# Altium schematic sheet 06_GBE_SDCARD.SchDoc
size A2; ApprovedBy: DNP; CheckedBy: DNP; Author: DNP; CompanyName: Google LLC; DrawnBy: DNP; Engineer: Bangfei/Michael/Leo; Organization: Google LLC; Address1: 1600 Amphitheatre Parkway; Address2: Mountain View, CA 94043; Address3: DNP; Address4: DNP; DocumentNumber: DNP; Revision: PVT; SheetNumber: 6; SheetTotal: 11; VersionControl_RevNumber: DNP; IsUserConfigurable: DNP
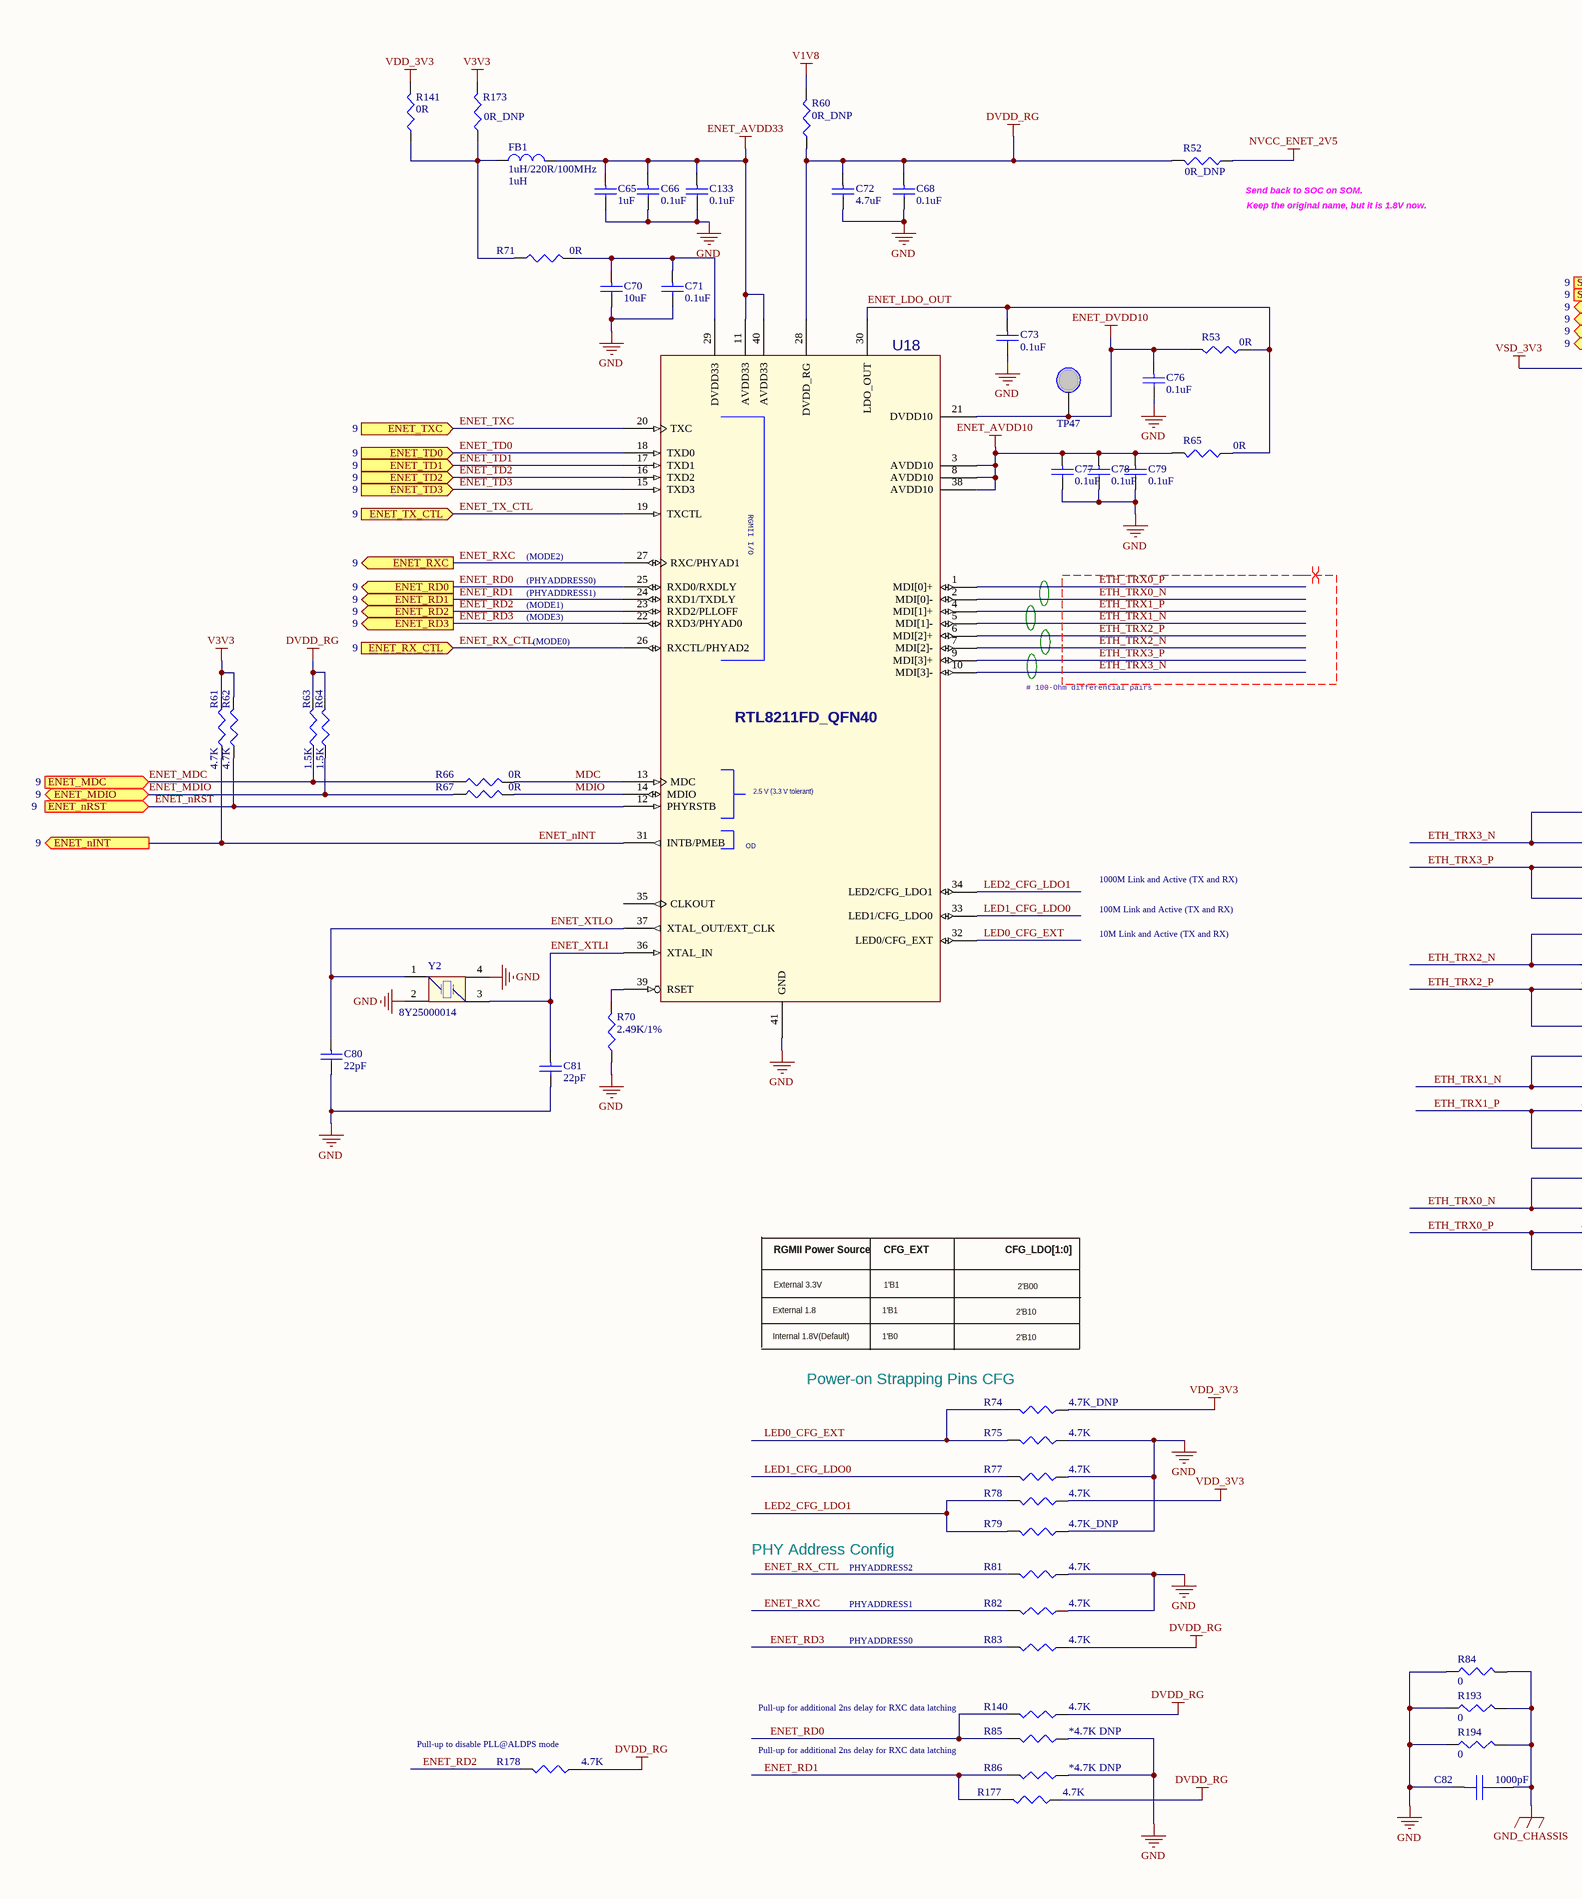
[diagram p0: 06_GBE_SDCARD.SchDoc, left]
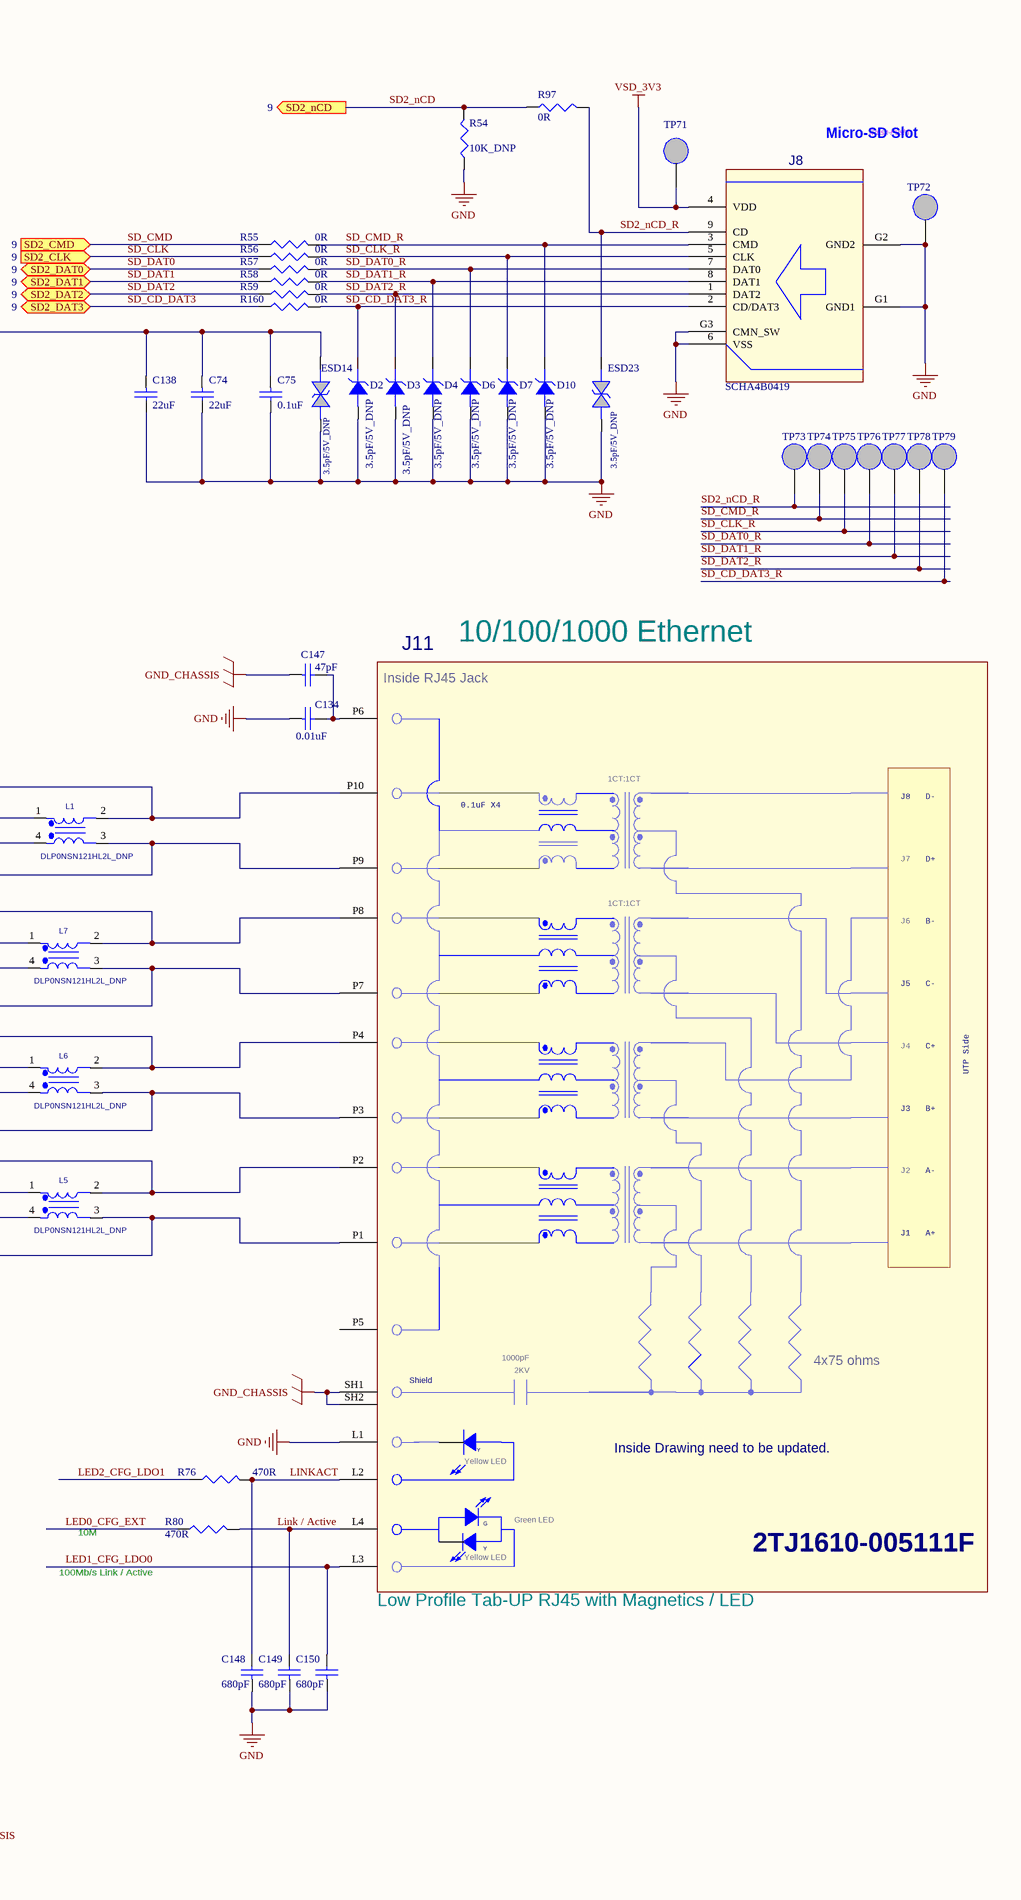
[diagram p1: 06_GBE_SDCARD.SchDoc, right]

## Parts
C65  value 1uF  [0201]  (hidden comment: 1uF/6.3V)
C66  value 0.1uF  [0201]  (hidden comment: 0.1uF/10V)
C68  value 0.1uF  [0201]  (hidden comment: 0.1uF/10V)
C70  value 10uF  [0402]  (hidden comment: 10uF/10V)
C71  value 0.1uF  [0201]  (hidden comment: 0.1uF/10V)
C72  value 4.7uF  [0402]  (hidden comment: 4.7uF/10V)
C73  value 0.1uF  [0201]  (hidden comment: 0.1uF/10V)
C74  value 22uF  [0603]  (hidden comment: 22uF/10V)
C75  value 0.1uF  [0201]  (hidden comment: 0.1uF/10V)
C76  value 0.1uF  [0201]  (hidden comment: 0.1uF/10V)
C77  value 0.1uF  [0201]  (hidden comment: 0.1uF/10V)
C78  value 0.1uF  [0201]  (hidden comment: 0.1uF/10V)
C79  value 0.1uF  [0201]  (hidden comment: 0.1uF/10V)
C80  value 22pF  [0201]  (hidden comment: 22pF/6.3V)
C81  value 22pF  [0201]  (hidden comment: 22pF/6.3V)
C82  value 1000pF  [1206]  (hidden comment: 1000pF/2KV)
C133  value 0.1uF  [0201]  (hidden comment: 0.1uF/10V)
C134  value 0.01uF  [0201]  (hidden comment: 0.01uF/25V)
C138  value 22uF  [0603]  (hidden comment: 22uF/10V)
C147  value 47pF  [0201]  (hidden comment: 47pF/25V)
C148  value 680pF  [0201]  (hidden comment: 680PF 25V)
C149  value 680pF  [0201]  (hidden comment: 680PF 25V)
C150  value 680pF  [0201]  (hidden comment: 680PF 25V)
D2  3.5pF/5V_DNP  [0201-Diode]
D3  3.5pF/5V_DNP  [0201-Diode]
D4  3.5pF/5V_DNP  [0201-Diode]
D6  3.5pF/5V_DNP  [0201-Diode]
D7  3.5pF/5V_DNP  [0201-Diode]
D10  3.5pF/5V_DNP  [0201-Diode]
ESD14  3.5pF/5V_DNP  [0201]
ESD23  3.5pF/5V_DNP  [0201]
FB1  1uH/220R/100MHz  value 1uH  [0603]
J8  SCHA4B0419  [CON9_SDCARD_8PIN_SCHA4B0419]
J11  2TJ1610-005111F  [RJ45-LED-2TJ1610-005111F]
L1  DLP0NSN121HL2L_DNP  [PL4-DLP0NSN121HL2L]
L5  DLP0NSN121HL2L_DNP  [PL4-DLP0NSN121HL2L]
L6  DLP0NSN121HL2L_DNP  [PL4-DLP0NSN121HL2L]
L7  DLP0NSN121HL2L_DNP  [PL4-DLP0NSN121HL2L]
R52  0R_DNP  [0201]
R53  0R  [0201]
R54  value 10K_DNP  [0201]  (hidden comment: 10K)
R55  0R  [0201]
R56  0R  [0201]
R57  0R  [0201]
R58  0R  [0201]
R59  0R  [0201]
R60  0R_DNP  [0201]
R61  4.7K  [0201]
R62  4.7K  [0201]
R63  1.5K  [0201]
R64  1.5K  [0201]
R65  0R  [0201]
R66  0R  [0201]
R67  0R  [0201]
R70  2.49K/1%  [0201]
R71  0R  [0201]
R74  4.7K_DNP  [0201]
R75  4.7K  [0201]
R76  470R  [0201]
R77  4.7K  [0201]
R78  4.7K  [0201]
R79  4.7K_DNP  [0201]
R80  470R  [0201]
R81  4.7K  [0201]
R82  4.7K  [0201]
R83  4.7K  [0201]
R84  value 0  [0805]  (hidden comment: R_0805_0)
R85  value *4.7K DNP  [0201]  (hidden comment: 4.7K)
R86  value *4.7K DNP  [0201]  (hidden comment: 4.7K)
R97  value 0R  [0201]  (hidden comment: 0R_DNP)
R140  value 4.7K  [0201]  (hidden comment: 4.7K_DNP)
R141  0R  [0201]
R160  0R  [0201]
R173  0R_DNP  [0201]
R177  value 4.7K  [0201]  (hidden comment: 4.7K_DNP)
R178  4.7K  [0201]
R193  value 0  [0805]  (hidden comment: R_0805_0)
R194  value 0  [0805]  (hidden comment: R_0805_0)
TP47  TP NM  [TP_SMD]  (value not drawn)  (no BOM)
TP71  TP NM  [TP_SMD]  (value not drawn)  (no BOM)
TP72  TP NM  [TP_SMD]  (value not drawn)  (no BOM)
TP73  TP NM  [TP3050]  (value not drawn)  (no BOM)
TP74  TP NM  [TP3050]  (value not drawn)  (no BOM)
TP75  TP NM  [TP3050]  (value not drawn)  (no BOM)
TP76  TP NM  [TP3050]  (value not drawn)  (no BOM)
TP77  TP NM  [TP3050]  (value not drawn)  (no BOM)
TP78  TP NM  [TP3050]  (value not drawn)  (no BOM)
TP79  TP NM  [TP3050]  (value not drawn)  (no BOM)
U18  RTL8211FD_QFN40  [QFN40-0_4-5X5-H0_9MM]
Y2  8Y25000014  [DFN130P250X50-4N]

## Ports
ENET_MDC (in, see 9), ENET_MDIO (bidir, see 9), ENET_nINT (out, see 9), ENET_nRST (in, see 9), ENET_RD0 (out, see 9), ENET_RD1 (out, see 9), ENET_RD2 (out, see 9), ENET_RD3 (out, see 9), ENET_RX_CTL (in, see 9), ENET_RXC (out, see 9), ENET_TD0 (in, see 9), ENET_TD1 (in, see 9), ENET_TD2 (in, see 9), ENET_TD3 (in, see 9), ENET_TX_CTL (in, see 9), ENET_TXC (in, see 9), SD2_CLK (in, see 9), SD2_CMD (in, see 9), SD2_DAT0 (bidir, see 9), SD2_DAT1 (bidir, see 9), SD2_DAT2 (bidir, see 9), SD2_DAT3 (bidir, see 9), SD2_nCD (out, see 9)

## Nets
DVDD_RG: C68.1 C72.1 R52.2 R60.1 R63.2 R64.2 R83.1 R140.1 R177.1 R178.1 U18.28(DVDD_RG)
ENET_AVDD10: C77.1 C78.1 C79.1 R65.2 U18.3(AVDD10) U18.8(AVDD10) U18.38(AVDD10)
ENET_AVDD33: C65.1 C66.1 C133.1 FB1.2 U18.11(AVDD33) U18.40(AVDD33)
ENET_DVDD10: C76.1 R53.2 TP47.1 U18.21(DVDD10)
GND: C65.2 C66.2 C68.2 C70.2 C71.2 C72.2 C73.2 C74.2 C75.2 C76.2 C77.2 C78.2 C79.2 C80.2 C81.2 C82.1 C133.2 C134.1 C138.2 C148.1 C149.1 C150.1 D2.A D3.A D4.A D6.A D7.A D10.A ESD14.1 ESD23.1 J8.6(VSS) J8.G1(GND1) J8.G2(GND2) J8.G3(CMN_SW) J11.L1 R54.1 R70.1 R75.1 R77.1 R79.1 R81.1 R82.1 R84.1 R85.1 R86.1 R193.1 R194.1 TP72.1 U18.41(GND) Y2.2 Y2.4
GND_CHASSIS: C82.2 C147.1 J11.SH1 J11.SH2 R84.2 R193.2 R194.2
NVCC_ENET_2V5: R52.1
V1V8: R60.2
V3V3: R61.2 R62.2 R173.2
VDD_3V3: R74.1 R78.1 R141.2
VSD_3V3: C74.1 C75.1 C138.1 ESD14.2 J8.4(VDD) TP71.1
ENET_LDO_OUT: C73.1 R53.1 R65.1 U18.30(LDO_OUT)
ENET_MDC: R63.1 R66.1 ; port ENET_MDC
ENET_MDIO: R64.1 R67.1 ; port ENET_MDIO
ENET_nINT: R61.1 U18.31(INTB/PMEB) ; port ENET_nINT
ENET_nRST: R62.1 U18.12(PHYRSTB) ; port ENET_nRST
ENET_RD0: R85.2 R140.2 U18.25(RXD0/RXDLY) ; port ENET_RD0
ENET_RD1: R86.2 R177.2 U18.24(RXD1/TXDLY) ; port ENET_RD1
ENET_RD2: R178.2 U18.23(RXD2/PLLOFF) ; port ENET_RD2
ENET_RD3: R83.2 U18.22(RXD3/PHYAD0) ; port ENET_RD3
ENET_RX_CTL: R81.2 U18.26(RXCTL/PHYAD2) ; port ENET_RX_CTL
ENET_RXC: R82.2 U18.27(RXC/PHYAD1) ; port ENET_RXC
ENET_TD0: U18.18(TXD0) ; port ENET_TD0
ENET_TD1: U18.17(TXD1) ; port ENET_TD1
ENET_TD2: U18.16(TXD2) ; port ENET_TD2
ENET_TD3: U18.15(TXD3) ; port ENET_TD3
ENET_TX_CTL: U18.19(TXCTL) ; port ENET_TX_CTL
ENET_TXC: U18.20(TXC) ; port ENET_TXC
ENET_XTLI: C81.1 U18.36(XTAL_IN) Y2.3(OSC3)
ENET_XTLO: C80.1 U18.37(XTAL_OUT/EXT_CLK) Y2.1(OSC1)
ETH_TRX0_N: J11.P2 L5.1 L5.2 U18.2(MDI[0]-)
ETH_TRX0_P: J11.P1 L5.3 L5.4 U18.1(MDI[0]+)
ETH_TRX1_N: J11.P4 L6.1 L6.2 U18.5(MDI[1]-)
ETH_TRX1_P: J11.P3 L6.3 L6.4 U18.4(MDI[1]+)
ETH_TRX2_N: J11.P8 L7.1 L7.2 U18.7(MDI[2]-)
ETH_TRX2_P: J11.P7 L7.3 L7.4 U18.6(MDI[2]+)
ETH_TRX3_N: J11.P10 L1.1 L1.2 U18.10(MDI[3]-)
ETH_TRX3_P: J11.P9 L1.3 L1.4 U18.9(MDI[3]+)
LED0_CFG_EXT: R74.2 R75.2 R80.1 U18.32(LED0/CFG_EXT)
LED1_CFG_LDO0: C150.2 J11.L3 R77.2 U18.33(LED1/CFG_LDO0)
LED2_CFG_LDO1: R76.1 R78.2 R79.2 U18.34(LED2/CFG_LDO1)
Link / Active: C149.2 J11.L4 R80.2
LINKACT: C148.2 J11.L2 R76.2
MDC: R66.2 U18.13(MDC)
MDIO: R67.2 U18.14(MDIO)
SD2_nCD: R54.2 R97.2 ; port SD2_nCD
SD2_nCD_R: ESD23.2 J8.9(CD) R97.1 TP73.1
SD_CD_DAT3: R160.1 ; port SD2_DAT3
SD_CD_DAT3_R: D2.K J8.2(CD/DAT3) R160.2 TP79.1
SD_CLK: R56.1 ; port SD2_CLK
SD_CLK_R: D7.K J8.5(CLK) R56.2 TP75.1
SD_CMD: R55.1 ; port SD2_CMD
SD_CMD_R: D10.K J8.3(CMD) R55.2 TP74.1
SD_DAT0: R57.1 ; port SD2_DAT0
SD_DAT0_R: D6.K J8.7(DAT0) R57.2 TP76.1
SD_DAT1: R58.1 ; port SD2_DAT1
SD_DAT1_R: D4.K J8.8(DAT1) R58.2 TP77.1
SD_DAT2: R59.1 ; port SD2_DAT2
SD_DAT2_R: D3.K J8.1(DAT2) R59.2 TP78.1
NetC70_1: C70.1 C71.1 R71.2 U18.29(DVDD33)
NetC134_2: C134.2 C147.2 J11.P6
NetFB1_1: FB1.1 R71.1 R141.1 R173.1
NetR70_2: R70.2 U18.39(RSET)

Not connected (* = marked no-connect by the designer): J11 P5; U18 35(CLKOUT)

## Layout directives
differential pair: ETH_TRX0_N, ETH_TRX0_P, ETH_TRX1_N, ETH_TRX1_P, ETH_TRX2_N, ETH_TRX2_P, ETH_TRX3_N, ETH_TRX3_P

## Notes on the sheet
- (near R52) Send back to SOC on SOM.
- (near R52) Keep the original name, but it is 1.8V now.
- Micro-SD Slot
- (Push-Push)
- (MODE2)
- (PHYADDRESS0)
- (PHYADDRESS1)
- (MODE1)
- (MODE3)
- (MODE0)
- # 100-Ohm differential pairs
- 10/100/1000 Ethernet
- 1000M Link and Active (TX and RX)
- 100M Link and Active (TX and RX)
- 10M Link and Active (TX and RX)
- RGMII Power Source
- CFG_EXT
- CFG_LDO[1:0]
- External 1.8
- External 3.3V
- 1'B1
- 2'B10
- 2'B00
- Internal 1.8V(Default)
- 1'B0
- (near R74) Power-on Strapping Pins CFG
- PHY Address Config
- 10M
- PHYADDRESS2
- PHYADDRESS1
- 100Mb/s Link / Active
- (near J11) Low Profile Tab-UP RJ45 with Magnetics / LED
- PHYADDRESS0
- Pull-up for additional 2ns delay for RXC data latching
- (near R178) Pull-up to disable PLL@ALDPS mode

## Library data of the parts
C65 = CAP_0201_1.0uF: CAP CER 1UF 6.3V 20% X5R 0201; MPN: C0603X5R0J105M030BC; QCI MPN: GRM033R60J105M; QPN: CH5101M9E02; QPN Description: CAP CHIP 1UF 6.3V(+-20%,X5R,0201); Function Code: LAN
C66 C68 C71 C73 C76-C79 C133 = CAP_0201_0.1uF: CAP CER 0.1UF 10V 10% X5R 0201; MPN: C0603X5R1A104K030BC; QCI MPN: GRM033R61A104K; QPN: CH4102K9E00; QPN Description: CAP CHIP 0.1U 10V(+-10%,X5R,0201); Function Code: LAN
C70 = CAP_0402_10uF: CAP CER 10UF 10V 20% X5R 0402; MPN: CL05A106MP5NUNC; QCI MPN: GRM155R61A106M; QPN: CH6102M9B00; QPN Description: CAP CHIP 10U 10V (+-20%, X5R, 0402)'; Function Code: LAN
C72 = CAP_0402_4.7uF: CAP CER 4.7UF 10V 20% X5R 0402; MPN: C1005X5R1A475M050BC; QCI MPN: GRM155R61A475M; QPN: CH5472M9B01; QPN Description: CAP CHIP 4.7U 10V(+-20%,X5R,0402); Function Code: LAN
C74 C138 = CAP_0603_22uF: CAP CER 22UF 6.3V 10% X5R 0603; MPN: CL10A226KQ8NRNE; QCI MPN: GRM188R61A226M; QPN: CH6222M9901; QPN Description: CAP CHIP 22UF 10V(+-20%,X5R,0603); Function Code: USB
C75 = CAP_0201_0.1uF: CAP CER 0.1UF 10V 10% X5R 0201; MPN: C0603X5R1A104K030BC; QCI MPN: GRM033R61A104K; QPN: CH4102K9E00; QPN Description: CAP CHIP 0.1U 10V(+-10%,X5R,0201); Function Code: SDC
C80 C81 = CAP_0201_22pF: CAP CER 22pF 6.3V 2% C0G NP0 0201; MPN: GJM0335C0J220GB01D; QCI MPN: GRM0335C1H220G; QPN: CH0226G0E00; QPN Description: CAP CHIP 22PF 50V(+-2%,COG,0201); Function Code: LAN
C82 = CAP_1206_1000pF_2KV: CAP CER 1000PF 2KV 10% 1206 X7R; MPN: CC1206KKX7RDBB102; QPN: CH2100IK212; QPN Description: CAP CHIP 1000P 2KV(+-10%,X7R,1206); Function Code: LAN
C134 = CAP_0201_0.1uF: CAP CHIP 0.01UF 25V(+-10%,X7R,0201); MPN: GRM033R71E103K; QPN: CH3104K1E01; Function Code: LAN
C147 = CAP_0201_47pF: CAP CER 47PF 25V 0201; MPN: GRM0335C1E470FA01D; QCI MPN: GRM0335C1E470J; QPN: CH0474J0E09; QPN Description: CAP CHIP 47P 25V(+-5%,COG,0201); Function Code: LCD
C148-C150 = CAP_0201_1.0nF: CAP CHIP 680PF 25V(+-10%,X7R,0201); MPN: GRM033R71E681K; QPN: CH1684K1E00; Function Code: SPK
D2-D4 D6 D7 D10 = Diode-ESDALC6V1-1U2: TVS DIODE 3V ST0201; MPN: DESD5V0V1BCSP-7; Function Code: SDC; QPN: BC5V0V1BZ02; QPN Description: DIODE ESD SMD DESD5V0V1BCSP-7 6V,DSN0603; DNP: V
ESD14 ESD23 = DIODE BI-DIR TRIG: DIODE TVS 15kV 10V 50A 8pF SMT RoHS; MPN: DESD5V0V1BCSP-7; QPN: BC5V0V1BZ02; QPN Description: DIODE ESD SMD DESD5V0V1BCSP-7 6V,DSN0603; Function Code: SDC; DNP: V
FB1 = INDUCTOR_BLM18EG221SN1D: FERRITE CHIP 220 OHM 2.0A 0603; QPN: CX8EG221011; QPN Description: EMI FILTER BLM18EG221SN1D(220,2A); Function Code: LAN
J8 = CONN_MICRO_SDCARD_8P_ALPS: CON SD CARD PUSH SMT 1.32mm 8pin; QPN: DFHS08FR182; QPN Description: CONN SMD MICRO SD CARD 8P FR(H1.45); Function Code: SDC
J11 = RJ45_Singatron_2TJ1610-005111F: CON 10 RJ45 SKT RA TH WITH G/Y LEDS 50MIL SP 611H -- 120L; Function Code: LAN; QPN: DFTJ14FR067; QPN Description: CONNDIP RJ45 14P2R FR(P2.54,H13.8)G/YLED
L1 L5-L7 = IND_CMC_DLW21: EMI FLTR DLP0NSN121HL2L(120,20%,90MA); QPN: CX121HL2000; Function Code: LAN
R52 R60 R173 = R_0201_0: RES SMD 0.0OHM JUMPER 1/20W 0201; MPN: ERJ-1GN0R00C; QCI MPN: RC0201JR-130RL; DNP: V; QPN: CS00001JE18; QPN Description: RES CHIP 0(1/20W,+-5%,0201); Function Code: LAN
R53 R65-R67 R71 R141 = R_0201_0: RES SMD 0.0OHM JUMPER 1/20W 0201; MPN: ERJ-1GN0R00C; QCI MPN: RC0201JR-130RL; QPN: CS00001JE18; QPN Description: RES CHIP 0(1/20W,+-5%,0201); Function Code: LAN
R54 = R_0201_10K: RES SMD 10K OHM JUMPER 1/20W  0201; MPN: ERJ-1GEF103C; QCI MPN: RC0201JR-1310KL; QPN: CS31001JE16; QPN Description: RES CHIP 10K 1/20W +-5%(0201); Function Code: SDC
R55-R59 R160 = R_0201_0: RES SMD 0.0OHM JUMPER 1/20W 0201; MPN: ERJ-1GN0R00C; QCI MPN: RC0201JR-130RL; QPN: CS00001JE18; QPN Description: RES CHIP 0(1/20W,+-5%,0201); Function Code: SDC
R61 R62 R75 R77 R78 R81-R83 R85 R86 R178 = R_0201_4.7K: RES SMD 4.7K OHM 1% 1/20W 0201; MPN: ERJ-1GEF4701C; QCI MPN: RC0201FR-134K7L; QPN: CS24701FE00; QPN Description: RES CHIP 4.7K 1/20W +-1%(0201; Function Code: LAN
R63 R64 = R_0201_1.5K: RES SMD 1.5K OHM JUMPER 1/20W  0201; MPN: ERJ-1GEJ6152C; QCI MPN: RC0201FR-071K5L; QPN: CS21501FE01; QPN Description: RES CHIP 1.5K 1/20W +-1%(0201); Function Code: LAN
R70 = R_0201_2.49K: RES SMD 2.49K OHM 1% 1/20W 0201; MPN: RC0201FR-132K49L; QCI MPN: RM02FTN2491; QPN: CS22491FE02; QPN Description: RES CHIP 2.49K(1/20W,+-1%,0201); Function Code: LAN
R74 = R_0201_4.7K: RES SMD 4.7K OHM 1% 1/20W 0201; MPN: ERJ-1GEF4701C; QCI MPN: RC0201FR-134K7L; DNP: V; QPN: CS24701FE00; QPN Description: RES CHIP 4.7K 1/20W +-1%(0201; Function Code: SDC
R76 R80 = R_0201_300: RES CHIP 470 1/20W +-5% (0201); MPN: RC0201JR-07470RL; QPN: CS14701JE00; Function Code: LAN
R79 R140 R177 = R_0201_4.7K: RES SMD 4.7K OHM 1% 1/20W 0201; MPN: ERJ-1GEF4701C; QCI MPN: RC0201FR-134K7L; DNP: V; QPN: CS24701FE00; QPN Description: RES CHIP 4.7K 1/20W +-1%(0201; Function Code: LAN
R84 R193 R194 = R_0805_0: RES SMD 0 OHM 1% 1/2W 0805
R97 = R_0201_0: RES SMD 0.0OHM JUMPER 1/20W 0201; MPN: ERJ-1GN0R00C; QCI MPN: RC0201JR-130RL; DNP: V; QPN: CS00001JE18; QPN Description: RES CHIP 0(1/20W,+-5%,0201); Function Code: SDC
TP47 TP71-TP79 = TP: TEST POIN
U18 = RTL8211FD_QFN40: IC XCVR ETHERNET PHY 10/100/1000G-BIT 3.3V QFN40; QCI MPN: RTL8211FD-CG; QPN: AL008211014; QPN Description: IC CTRL(40P)RTL8211FD-CG(QFN); Function Code: LAN
Y2 = XTAL_25MHZ_ABM10AIG-25.000MHZ-4Z-T3: Crystal 25.0000MHz 30ppm 10pF 60 Ohm -40蚓 - 125蚓 Surface Mount 4-SMD, No Lead (DFN, LCC); Function Code: LAN; QPN: BG6250000B5; QPN Description: XTAL SMD 25MHZ(+-10PPM,16PF)8Y25000014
